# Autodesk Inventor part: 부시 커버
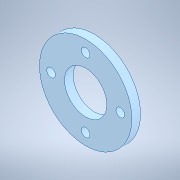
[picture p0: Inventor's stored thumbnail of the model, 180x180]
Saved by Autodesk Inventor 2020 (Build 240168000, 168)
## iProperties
Created: 2024-05
Part Number: 부시 커버
Material: 강철, 연강
Document SubType Name: Modeling
Designer: oem
Density: 7.85 g/cm^3
Appearance: 기본값
Author: jhkim
Sending System: Autodesk Inventor 2025
Preprocessor: ST-DEVELOPER v20
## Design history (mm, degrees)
feature "솔리드1"
node "솔리드2"
